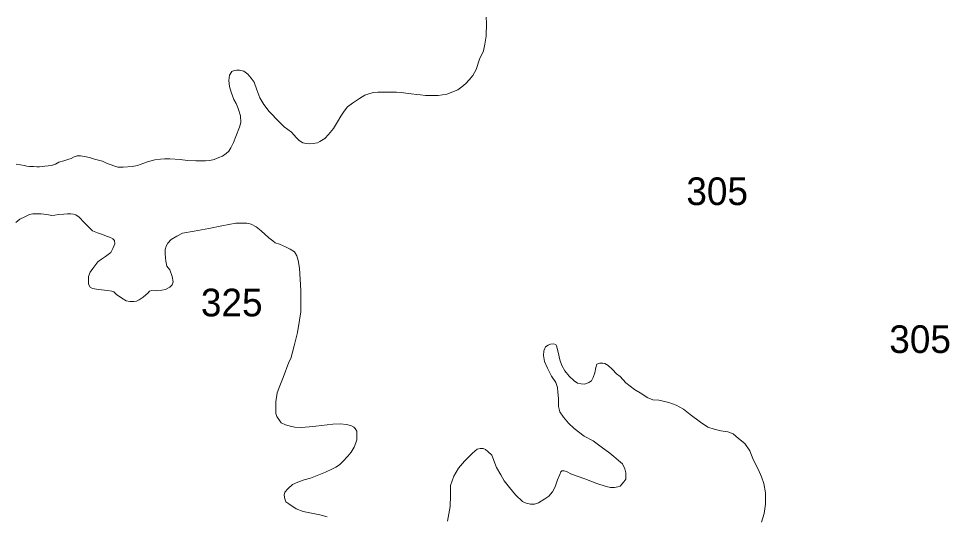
# Model space of a CAD drawing. Extents: x 445.4 to 500, y 8728.7 to 8784.
# Drawn here: x 467.93 to 473.32, y 8749.77 to 8752.65 of the extents above; entities that cross this region are included whole.
import ezdxf

# ---------------------------------------------------------------- set-up
doc = ezdxf.new("R2010")
doc.units = 0
doc.header["$LTSCALE"] = 0.064
doc.layers.add('2', color=7, linetype='Continuous', lineweight=13)
doc.layers.add('21', color=7, linetype='Continuous')

msp = doc.modelspace()

# ---------------------------------------------------------------- linework, layer by layer
at = {"layer": '2'}
for points in [[(470.3119, 8752.2036), (470.3392, 8752.2026), (470.3627, 8752.2026), (470.4129, 8752.2116), (470.4772, 8752.235), (470.5006, 8752.2525), (470.5231, 8752.2729), (470.5426, 8752.2934), (470.564, 8752.3187), (470.5835, 8752.3527), (470.6022, 8752.4125), (470.6246, 8752.4622), (470.6324, 8752.4992), (470.6412, 8752.5459), (470.6432, 8752.6214), (470.6403, 8752.6564)], [(467.9977, 8751.7924), (468.0196, 8751.7924), (468.0398, 8751.7906), (468.0538, 8751.7906), (468.0863, 8751.7933), (468.1246, 8751.7985), (468.1465, 8751.8055), (468.1675, 8751.8169), (468.1956, 8751.8257), (468.2184, 8751.8327), (468.2386, 8751.8388), (468.2553, 8751.8484), (468.2737, 8751.8528), (468.293, 8751.8528), (468.3158, 8751.8502), (468.3447, 8751.8449), (468.3737, 8751.8344), (468.4193, 8751.823), (468.4474, 8751.8099), (468.4702, 8751.802), (468.486, 8751.795), (468.5088, 8751.7889), (468.5395, 8751.788), (468.5917, 8751.7924), (468.6215, 8751.7977), (468.6435, 8751.8064), (468.6803, 8751.8187), (468.7233, 8751.8301), (468.7549, 8751.8345), (468.7794, 8751.8362), (468.8084, 8751.8362), (468.8698, 8751.8327), (468.911, 8751.8266), (468.9607, 8751.824), (469.0159, 8751.8249), (469.0405, 8751.8275), (469.0651, 8751.8328), (469.094, 8751.8433), (469.1151, 8751.8512), (469.1352, 8751.8669), (469.1501, 8751.8809), (469.1633, 8751.9002), (469.1782, 8751.9317), (469.1923, 8751.9659), (469.2136, 8752.02), (469.2197, 8752.0471), (469.218, 8752.0856), (469.2057, 8752.1285), (469.1925, 8752.1574), (469.1802, 8752.1802), (469.1653, 8752.2219), (469.1539, 8752.256), (469.1504, 8752.2893), (469.1557, 8752.3208), (469.1679, 8752.3427), (469.182, 8752.348), (469.196, 8752.3497), (469.2127, 8752.3488), (469.2381, 8752.3436), (469.2601, 8752.3261), (469.2811, 8752.3033), (469.2969, 8752.2797), (469.3127, 8752.2359), (469.3302, 8752.1886), (469.353, 8752.151), (469.3846, 8752.1098), (469.4428, 8752.0497), (469.4709, 8752.0225), (469.513, 8751.991), (469.5437, 8751.9586), (469.5578, 8751.9428), (469.5797, 8751.9297), (469.599, 8751.9245), (469.6157, 8751.9236), (469.6402, 8751.9253), (469.6639, 8751.9288), (469.6788, 8751.9358), (469.7069, 8751.9533), (469.7271, 8751.9779), (469.7578, 8752.0129), (469.7806, 8752.0497), (469.7999, 8752.0838), (469.8192, 8752.1118), (469.839, 8752.1376), (469.8671, 8752.1594), (469.9083, 8752.1857), (469.939, 8752.2058), (469.9677, 8752.2152), (469.9892, 8752.2201), (470.0135, 8752.2221), (470.0408, 8752.223), (470.0652, 8752.2221), (470.0945, 8752.2221), (470.1218, 8752.2221), (470.1491, 8752.2201), (470.1754, 8752.2172), (470.2066, 8752.2123), (470.2388, 8752.2084), (470.2603, 8752.2065), (470.2905, 8752.2036), (470.3119, 8752.2036)], [(467.9196, 8751.8047), (467.9441, 8751.8012), (467.9661, 8751.7977), (467.981, 8751.7941), (467.9977, 8751.7924)], [(468.4146, 8751.2558), (468.4373, 8751.2702), (468.4685, 8751.2949), (468.4793, 8751.3164), (468.4901, 8751.3451), (468.4889, 8751.363), (468.4793, 8751.3726), (468.4661, 8751.381), (468.4434, 8751.3893), (468.4194, 8751.3989), (468.3907, 8751.4084), (468.3608, 8751.4204), (468.3428, 8751.4383), (468.3141, 8751.4682), (468.2836, 8751.4995), (468.2656, 8751.5126), (468.2524, 8751.5162), (468.2357, 8751.5186), (468.2177, 8751.5174), (468.195, 8751.5162), (468.165, 8751.5138), (468.1435, 8751.5102), (468.1255, 8751.509), (468.1076, 8751.5114), (468.0944, 8751.5138), (468.0645, 8751.5174), (468.0417, 8751.5186), (468.0154, 8751.5186), (467.9962, 8751.5138), (467.9699, 8751.5006), (467.9412, 8751.4875), (467.9172, 8751.4684)], [(469.7712, 8750.0515), (469.7909, 8750.0649), (469.8115, 8750.0835), (469.8398, 8750.1152), (469.8584, 8750.1379), (469.876, 8750.1668), (469.8863, 8750.1926), (469.8915, 8750.2091), (469.8926, 8750.2339), (469.8914, 8750.2598), (469.8819, 8750.2749), (469.8744, 8750.2824), (469.8573, 8750.2919), (469.8308, 8750.2976), (469.7968, 8750.3013), (469.7532, 8750.2994), (469.7211, 8750.2957), (469.6548, 8750.2881), (469.617, 8750.2843), (469.5696, 8750.2806), (469.5337, 8750.2824), (469.5129, 8750.2862), (469.4788, 8750.2957), (469.4542, 8750.3089), (469.4296, 8750.3448), (469.4239, 8750.3618), (469.4238, 8750.3849), (469.4226, 8750.4303), (469.431, 8750.4817), (469.4453, 8750.5223), (469.4657, 8750.5701), (469.4993, 8750.6594), (469.51, 8750.6798), (469.5292, 8750.7538), (469.5484, 8750.8303), (469.5604, 8750.9016), (469.5676, 8750.9506), (469.5676, 8751.0127), (469.5688, 8751.0737), (469.5592, 8751.2034), (469.5531, 8751.247), (469.5447, 8751.2745), (469.5303, 8751.2972), (469.5052, 8751.314), (469.48, 8751.3271), (469.4441, 8751.3414), (469.4202, 8751.3498), (469.4058, 8751.3618), (469.3819, 8751.3785), (469.3376, 8751.4203), (469.3096, 8751.4421), (469.2797, 8751.4576), (469.2545, 8751.4636), (469.2258, 8751.4648), (469.1911, 8751.4648), (469.1109, 8751.4481), (469.0354, 8751.4325), (468.9504, 8751.4182), (468.8834, 8751.4062), (468.8499, 8751.3883), (468.8163, 8751.3692), (468.7984, 8751.3489), (468.7888, 8751.3298), (468.7828, 8751.3118), (468.7828, 8751.2891), (468.7852, 8751.264), (468.7864, 8751.2437), (468.7922, 8751.2156), (468.8089, 8751.1941), (468.8233, 8751.1547), (468.8293, 8751.1236), (468.8221, 8751.1069), (468.8101, 8751.0926), (468.785, 8751.0806), (468.7635, 8751.0758), (468.7347, 8751.0722), (468.706, 8751.0746), (468.6916, 8751.0711), (468.6844, 8751.0615), (468.654, 8751.0348), (468.6325, 8751.0192), (468.6169, 8751.0121), (468.6001, 8751.0097), (468.5774, 8751.0097), (468.5558, 8751.0145), (468.5307, 8751.0288), (468.5008, 8751.0503), (468.4852, 8751.0658), (468.4744, 8751.0706), (468.4481, 8751.0742), (468.3966, 8751.0802), (468.3738, 8751.0838), (468.3619, 8751.0862), (468.3475, 8751.0933), (468.3391, 8751.1113), (468.3379, 8751.1304), (468.3379, 8751.1555), (468.3475, 8751.1794), (468.3643, 8751.2021), (468.3918, 8751.2391), (468.4146, 8751.2558)], [(472.2345, 8749.7332), (472.2505, 8749.7838), (472.2576, 8749.8376), (472.2576, 8749.9028), (472.249, 8749.9567), (472.2348, 8749.9963), (472.2164, 8750.0388), (472.1865, 8750.0964), (472.1681, 8750.146), (472.1383, 8750.1886), (472.1013, 8750.2169), (472.0715, 8750.2452), (472.0403, 8750.2566), (471.9991, 8750.2608), (471.9608, 8750.2707), (471.9239, 8750.2821), (471.8827, 8750.3118), (471.8231, 8750.3572), (471.7842, 8750.3876), (471.7402, 8750.4103), (471.699, 8750.4259), (471.6408, 8750.4386), (471.6067, 8750.4415), (471.5741, 8750.4542), (471.5414, 8750.4755), (471.5003, 8750.501), (471.4491, 8750.5393), (471.4161, 8750.5756), (471.3948, 8750.5926), (471.3721, 8750.6167), (471.3479, 8750.6407), (471.3281, 8750.6507), (471.3167, 8750.6535), (471.2997, 8750.6535), (471.2812, 8750.6478), (471.2769, 8750.628), (471.2698, 8750.5982), (471.2599, 8750.5699), (471.2514, 8750.5515), (471.2358, 8750.5416), (471.2116, 8750.5316), (471.1918, 8750.533), (471.169, 8750.5373), (471.1506, 8750.5515), (471.1222, 8750.5784), (471.0966, 8750.6096), (471.0782, 8750.6393), (471.0668, 8750.6733), (471.0569, 8750.7173), (471.0477, 8750.7543), (471.0435, 8750.7614), (471.0307, 8750.7656), (471.0137, 8750.7642), (471.0009, 8750.7585), (470.9853, 8750.7486), (470.9753, 8750.7245), (470.9739, 8750.6976), (470.9796, 8750.6636), (470.9966, 8750.6253), (471.0193, 8750.5772), (471.0435, 8750.5417), (471.0548, 8750.5134)], [(471.0548, 8750.5134), (471.0562, 8750.485), (471.059, 8750.4489), (471.0605, 8750.4021), (471.0676, 8750.3709), (471.0889, 8750.3412), (471.1172, 8750.3058), (471.1513, 8750.2746), (471.2085, 8750.2315), (471.2597, 8750.2031), (471.3065, 8750.1691), (471.3576, 8750.1323), (471.3803, 8750.1124), (471.4073, 8750.0897), (471.43, 8750.0713), (471.4431, 8750.0409), (471.4502, 8750.0182), (471.4502, 8750.0012), (471.4488, 8749.9828), (471.4388, 8749.9658), (471.4175, 8749.9417), (471.4033, 8749.9374), (471.3834, 8749.9332), (471.3607, 8749.9332), (471.3366, 8749.9388), (471.2826, 8749.9573), (471.2117, 8749.9842), (471.135, 8750.0111), (471.1059, 8750.0266), (471.0932, 8750.0308), (471.079, 8750.0294), (471.0733, 8750.0238), (471.0676, 8750.0096), (471.0548, 8749.9784), (471.0406, 8749.9373), (471.025, 8749.909), (471.0037, 8749.8835), (470.981, 8749.8679), (470.9441, 8749.8452), (470.92, 8749.8367), (470.8972, 8749.8381), (470.8731, 8749.8424), (470.8504, 8749.8523), (470.8106, 8749.892), (470.7766, 8749.9345), (470.7453, 8749.9713), (470.7254, 8750.0068), (470.7013, 8750.0493), (470.6736, 8750.1201), (470.6509, 8750.1414), (470.6367, 8750.1527), (470.6239, 8750.1598), (470.6055, 8750.1598), (470.5884, 8750.1556), (470.5614, 8750.1329), (470.516, 8750.0861), (470.4805, 8750.045), (470.4535, 8749.9983), (470.4337, 8749.9458), (470.4337, 8749.8877), (470.4322, 8749.824), (470.4166, 8749.7394)], [(469.7199, 8749.7636), (469.6787, 8749.7749), (469.5821, 8749.7948), (469.541, 8749.8103), (469.4984, 8749.8387), (469.4816, 8749.8512), (469.4744, 8749.8678), (469.4713, 8749.8884), (469.4744, 8749.906), (469.493, 8749.9266), (469.5189, 8749.9503), (469.5509, 8749.9638), (469.5871, 8749.9782), (469.6243, 8749.9875), (469.7112, 8750.0216), (469.7505, 8750.0412), (469.7712, 8750.0515)]]:
    msp.add_lwpolyline(points, dxfattribs=at)

# ---------------------------------------------------------------- texts
at = {"layer": '21'}
for s, p in [('305', (471.8, 8751.5688)), ('325', (468.9893, 8750.9244)), ('305', (472.9751, 8750.7124))]:
    msp.add_text(s, height=0.16, dxfattribs=at).set_placement(p)

doc.saveas('drawing.dxf')
